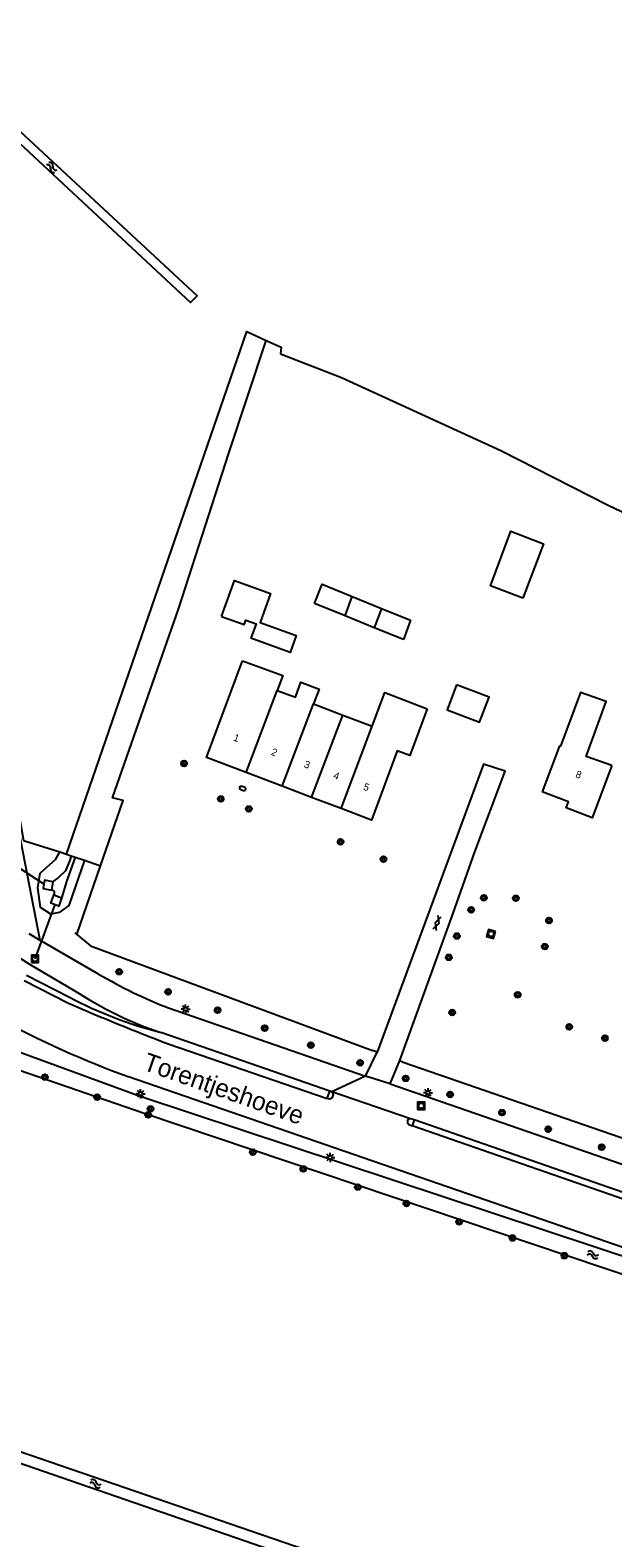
# Model space of a CAD drawing. Extents: x 135990 to 139000, y 393500 to 396000.
# Drawn here: x 136517.1 to 136597.2, y 395122 to 395329.5 of the extents above; entities that cross this region are included whole.
import ezdxf

# ---------------------------------------------------------------- set-up
doc = ezdxf.new("R2010")
doc.units = 0
for name, color, linetype in [('gg-afsc-draadraster', 7, 'Continuous'), ('gg-afsc-erfafscheiding', 7, 'Continuous'), ('gg-afsc-hekwerk', 7, 'Continuous'), ('gg-anno-huisnummerreeks BGT', 7, 'Continuous'), ('gg-anno-openbare ruimte label', 7, 'Continuous'), ('gg-bbg-bijgebouw', 7, 'Continuous'), ('gg-bbg-gedigitaliseerde bebouwing', 7, 'Continuous'), ('gg-bbg-gedigitaliseerde bijgebouw', 7, 'Continuous'), ('gg-bbg-hoofdgebouw', 7, 'Continuous'), ('gg-bbg-luifel en loopbrug', 7, 'Continuous'), ('gg-bbg-tussenscheiding', 7, 'Continuous'), ('gg-knt-bronhoudergrens', 7, 'Continuous'), ('gg-knt-verharding', 7, 'Continuous'), ('gg-knt-verharding nz', 7, 'Continuous'), ('gg-kntw-bovenkant insteek waterloop', 7, 'Continuous'), ('gg-kwrk-duiker nz buis', 7, 'Continuous'), ('gg-kwrk-faunavoorziening', 7, 'Continuous'), ('gt-grn-groengrens', 7, 'Continuous'), ('gt-grn-vlakafsluiter', 7, 'Continuous'), ('gt-grn-weggrens', 7, 'Continuous'), ('gt-symb-boom', 7, 'Continuous'), ('gt-symb-brandkraan', 7, 'Continuous'), ('gt-symb-gesloten verharding', 7, 'Continuous'), ('gt-symb-lichtmast', 7, 'Continuous'), ('gt-symb-rioolschacht', 7, 'Continuous'), ('gt-symb-watersymbool', 7, 'Continuous'), ('gx-grn-maaiveld', 7, 'Continuous')]:
    doc.layers.add(name, color=color, linetype=linetype)

# ---------------------------------------------------------------- blocks, each defined once
blk = doc.blocks.new('gt0-BOOM')
at = {"layer": 'gt-symb-boom'}
for radius in [0.4, 0.2]:
    blk.add_circle((0, 0), radius, dxfattribs=at)
blk = doc.blocks.new('gt0-BR')
at = {"layer": 'gt-symb-brandkraan'}
for centre, radius, start, end in [((-0.24, 0), 0.206, 107.5669, 252.4331), ((0.6, -2.66), 3, 106.892, 107.5669), ((0, -0.69), 0.938, 73.108, 106.892), ((-0.6, -2.66), 3, 72.4331, 73.108), ((0.24, 0), 0.206, 287.567, 72.4331), ((0.6, 2.66), 3, 252.4331, 253.108), ((0, 0.69), 0.938, 253.108, 286.8921), ((-0.6, 2.66), 3, 286.8921, 287.567)]:
    blk.add_arc(centre, radius, start, end, dxfattribs=at)
blk = doc.blocks.new('gt0-WA')
at = {"layer": 'gt-symb-watersymbool'}
for centre, start, end in [((-0.32, 0.02), 28.0725, 151.9275), ((0.43, 0.42), 208.0725, 331.9275), ((-0.32, -0.43), 28.0725, 151.9275), ((0.43, -0.03), 208.0725, 331.9275)]:
    blk.add_arc(centre, 0.425, start, end, dxfattribs=at)
blk = doc.blocks.new('gt0-RS')
at = {"layer": 'gt-symb-rioolschacht'}
blk.add_lwpolyline([(-0.5, -0.5), (0.5, -0.5), (0.5, 0.5), (-0.5, 0.5)], close=True, dxfattribs=at)
blk.add_circle((0, 0), 0.375, dxfattribs=at)
blk = doc.blocks.new('gt0-LMAST')
at = {"layer": 'gt-symb-lichtmast'}
for p, q in [((-0.18, 0.17), (-0.45, 0.44)), ((-0.01, 0.25), (-0.01, 0.62)), ((0.17, 0.17), (0.44, 0.44)), ((-0.26, 0), (-0.63, 0)), ((-0.18, -0.18), (-0.45, -0.45)), ((-0.01, -0.25), (-0.01, -0.63)), ((0.44, -0.45), (0.17, -0.18)), ((0.24, 0), (0.62, 0))]:
    blk.add_line(p, q, dxfattribs=at)
blk.add_circle((-0.01, 0), 0.25, dxfattribs=at)
blk = doc.blocks.new('gt0-GESVH1')
at = {"layer": 'gt-symb-gesloten verharding'}
for p, q in [((-0.99, -0.26), (0.01, 0.24)), ((0.01, -0.26), (-0.99, 0.24)), ((0.01, 0.24), (1.01, -0.26)), ((1.01, 0.24), (0.01, -0.26))]:
    blk.add_line(p, q, dxfattribs=at)

msp = doc.modelspace()

# ---------------------------------------------------------------- linework, layer by layer
at = {"layer": 'gg-afsc-draadraster'}
msp.add_lwpolyline([(136513.026, 395235.571), (136516.127, 395218.022), (136521.138, 395216.455)], dxfattribs=at)
at = {"layer": 'gg-afsc-erfafscheiding'}
msp.add_line((136523.466, 395205.085), (136526.733, 395214.516), dxfattribs=at)
for points in [[(136526.733, 395214.516), (136529.857, 395223.532), (136528.408, 395223.874), (136537.53, 395250), (136544.405, 395271.297), (136549.544, 395286.842)], [(136549.544, 395286.842), (136551.592, 395285.897), (136551.492, 395284.97), (136559.907, 395281.749)]]:
    msp.add_lwpolyline(points, dxfattribs=at)
at = {"layer": 'gg-afsc-hekwerk'}
for p, q in [((136523.195, 395205.314), (136523.466, 395205.085)), ((136568.379, 395187.481), (136612.594, 395172.192))]:
    msp.add_line(p, q, dxfattribs=at)
msp.add_lwpolyline([(136523.466, 395205.085), (136525.36, 395203.485), (136564.149, 395189.095)], dxfattribs=at)
msp.add_lwpolyline([(136523.466, 395205.085), (136525.36, 395203.485), (136564.149, 395189.095)], dxfattribs=at)
at = {"layer": 'gg-bbg-bijgebouw'}
msp.add_lwpolyline([(136543.406, 395248.86), (136546.527, 395247.753), (136546.734, 395248.337), (136548.161, 395247.837), (136547.443, 395245.845)], dxfattribs=at)
at = {"layer": 'gg-bbg-gedigitaliseerde bebouwing'}
for p, q in [((136556.03, 395236.797), (136560.08, 395235.264)), ((136560.08, 395235.264), (136564.129, 395233.731))]:
    msp.add_line(p, q, dxfattribs=at)
for points in [[(136546.283, 395242.74), (136551.852, 395240.731), (136551.073, 395238.673)], [(136551.073, 395238.673), (136553.551, 395237.735), (136554.33, 395239.793), (136556.809, 395238.854), (136556.03, 395236.797)], [(136564.129, 395233.731), (136565.88, 395238.356), (136571.714, 395236.147)], [(136597.125, 395228.316), (136593.591, 395229.589), (136596.305, 395237.12), (136592.813, 395238.379), (136590.028, 395230.973), (136589.916, 395231.015)]]:
    msp.add_lwpolyline(points, dxfattribs=at)
at = {"layer": 'gg-bbg-gedigitaliseerde bijgebouw'}
for p, q in [((136560.402, 395248.92), (136556.172, 395250.632)), ((136561.386, 395251.586), (136565.402, 395249.961)), ((136564.417, 395247.295), (136560.402, 395248.92)), ((136565.402, 395249.961), (136569.417, 395248.336)), ((136569.417, 395248.336), (136568.433, 395245.67)), ((136568.433, 395245.67), (136564.417, 395247.295))]:
    msp.add_line(p, q, dxfattribs=at)
for points in [[(136584.878, 395251.38), (136580.389, 395253.08), (136583.222, 395260.562), (136587.711, 395258.862), (136584.878, 395251.38)], [(136543.406, 395248.86), (136545.19, 395253.81), (136550.145, 395252.024), (136548.696, 395248.003), (136553.685, 395246.205), (136552.852, 395243.896), (136547.443, 395245.845)], [(136556.172, 395250.632), (136557.238, 395253.265), (136561.386, 395251.586)]]:
    msp.add_lwpolyline(points, dxfattribs=at)
at = {"layer": 'gg-bbg-hoofdgebouw'}
for p, q in [((136589.916, 395231.015), (136587.518, 395224.706)), ((136551.743, 395225.473), (136546.786, 395227.35)), ((136555.793, 395223.94), (136551.743, 395225.473)), ((136559.842, 395222.407), (136555.793, 395223.94))]:
    msp.add_line(p, q, dxfattribs=at)
for points in [[(136546.786, 395227.35), (136541.321, 395229.419), (136546.283, 395242.74)], [(136571.714, 395236.147), (136569.317, 395229.689), (136567.564, 395230.339), (136564.032, 395220.821), (136559.842, 395222.407)], [(136597.125, 395228.316), (136594.401, 395221.12), (136590.81, 395222.481), (136591.134, 395223.336), (136587.518, 395224.706)]]:
    msp.add_lwpolyline(points, dxfattribs=at)
at = {"layer": 'gg-bbg-luifel en loopbrug'}
msp.add_lwpolyline([(136575.737, 395239.448), (136574.427, 395235.988), (136578.916, 395234.288), (136580.226, 395237.749), (136575.737, 395239.448)], dxfattribs=at)
at = {"layer": 'gg-bbg-tussenscheiding'}
for p, q in [((136560.402, 395248.92), (136561.386, 395251.586)), ((136565.402, 395249.961), (136564.417, 395247.295)), ((136546.786, 395227.35), (136551.073, 395238.673)), ((136551.743, 395225.473), (136556.03, 395236.797)), ((136555.793, 395223.94), (136560.08, 395235.264)), ((136559.842, 395222.407), (136564.129, 395233.731))]:
    msp.add_line(p, q, dxfattribs=at)
at = {"layer": 'gg-knt-bronhoudergrens'}
for points in [[(136522.075, 395216.13), (136546.859, 395288.081), (136549.544, 395286.842)], [(136559.907, 395281.749), (136581.845, 395271.703), (136596.522, 395264.214), (136613.351, 395256.16), (136628.985, 395247.516), (136658.062, 395233.532), (136638.935, 395197.21), (136632.303, 395184.373)]]:
    msp.add_lwpolyline(points, dxfattribs=at)
at = {"layer": 'gg-knt-verharding'}
for p, q in [((136526.487, 395199.622), (136518.408, 395204.306)), ((136516.222, 395198.725), (136522.342, 395195.596)), ((136536.116, 395194.959), (136563.224, 395185.586)), ((136558.315, 395183.484), (136535.061, 395191.575)), ((136536.042, 395190.022), (136557.951, 395182.509)), ((136563.224, 395185.586), (136564.802, 395188.868)), ((136566.604, 395184.488), (136567.914, 395187.715)), ((136566.604, 395184.488), (136611.728, 395168.872)), ((136558.573, 395183.388), (136558.315, 395183.484)), ((136569.899, 395179.573), (136569.283, 395179.737)), ((136606.737, 395165.815), (136569.628, 395178.712)), ((136607.083, 395166.615), (136569.899, 395179.573))]:
    msp.add_line(p, q, dxfattribs=at)
for points in [[(136432.39, 395264.294), (136433.511, 395264.036), (136472.135, 395233.888), (136499.013, 395212.991), (136506.933, 395207.381), (136516.981, 395200.985), (136523.116, 395197.378)], [(136512.623, 395235.47), (136515.741, 395217.994), (136518.408, 395204.306)], [(136567.914, 395187.715), (136575.247, 395207.884), (136578.24, 395216.451), (136582.42, 395227.53), (136579.44, 395228.492), (136564.802, 395188.868)], [(136530.57, 395185.504), (136645.545, 395145.829), (136708.224, 395124.253)], [(136558.573, 395183.388), (136558.771, 395183.014), (136558.586, 395182.522), (136558.296, 395182.406), (136557.951, 395182.509)], [(136569.283, 395179.737), (136569.007, 395179.52), (136568.975, 395179.19), (136569.151, 395178.935), (136569.628, 395178.712)]]:
    msp.add_lwpolyline(points, dxfattribs=at)
for centre, radius, start, end in [((136558.725, 395253.92), 63.147, 239.30117, 249.02015), ((136551.211, 395240.013), 51.059, 236.61688, 251.56123), ((136664.516, 395525.414), 359.156, 246.68065, 249.04034), ((136577.879, 395314.973), 137.842, 241.75464, 249.92711)]:
    msp.add_arc(centre, radius, start, end, dxfattribs=at)
at = {"layer": 'gg-knt-verharding nz'}
for p, q in [((136516.896, 395205.183), (136518.408, 395204.306)), ((136566.604, 395184.488), (136563.224, 395185.586)), ((136569.283, 395179.737), (136558.573, 395183.388))]:
    msp.add_line(p, q, dxfattribs=at)
at = {"layer": 'gg-kntw-bovenkant insteek waterloop'}
for points in [[(136500.168, 395329.546), (136499.79, 395329.208), (136499.937, 395328.514), (136539.135, 395292.051), (136540.047, 395292.962), (136500.848, 395329.312), (136500.168, 395329.546)], [(136524.518, 395215.284), (136522.359, 395209.05), (136521.029, 395208.086), (136519.914, 395207.866), (136518.463, 395208.784), (136518.125, 395211.502), (136518.448, 395213.486), (136520.615, 395215.427), (136521.138, 395216.455)], [(136499.93, 395194.624), (136532.19, 395182.83), (136601.724, 395159.802)], [(136600.918, 395157.47), (136532.89, 395180.4), (136497.97, 395192.383)], [(136473.831, 395146.756), (136577.715, 395110.851), (136578.232, 395112.345), (136474.559, 395147.97), (136473.831, 395146.756)]]:
    msp.add_lwpolyline(points, dxfattribs=at)
at = {"layer": 'gg-kwrk-duiker nz buis'}
for p, q in [((136512.72, 395216.078), (136518.983, 395212.014)), ((136520.44, 395209.208), (136517.724, 395201.706))]:
    msp.add_line(p, q, dxfattribs=at)
at = {"layer": 'gg-kwrk-faunavoorziening'}
for p, q in [((136520.193, 395212.318), (136519.981, 395211.164)), ((136521.385, 395210.078), (136520.315, 395210.462))]:
    msp.add_line(p, q, dxfattribs=at)
for points in [[(136520.193, 395212.318), (136519.043, 395212.529), (136518.83, 395211.375), (136519.981, 395211.164)], [(136521.385, 395210.078), (136520.989, 395208.977), (136519.919, 395209.361), (136520.315, 395210.462)]]:
    msp.add_lwpolyline(points, dxfattribs=at)
at = {"layer": 'gt-grn-groengrens'}
for p, q in [((136516.535, 395199.461), (136522.487, 395196.419)), ((136557.951, 395182.509), (136558.315, 395183.484)), ((136569.899, 395179.573), (136569.628, 395178.712))]:
    msp.add_line(p, q, dxfattribs=at)
msp.add_arc((136549.656, 395248.201), 58.477, 242.31532, 255.54738, dxfattribs=at)
at = {"layer": 'gt-grn-vlakafsluiter'}
for p, q in [((136521.138, 395216.455), (136522.075, 395216.13)), ((136524.518, 395215.284), (136526.733, 395214.516)), ((136564.802, 395188.868), (136564.149, 395189.095)), ((136567.914, 395187.715), (136568.379, 395187.481))]:
    msp.add_line(p, q, dxfattribs=at)
at = {"layer": 'gt-grn-weggrens'}
msp.add_line((136563.224, 395185.586), (136558.573, 395183.388), dxfattribs=at)
at = {"layer": 'gx-grn-maaiveld'}
for p, q in [((136522.075, 395216.13), (136522.711, 395215.91)), ((136522.711, 395215.91), (136523.254, 395215.722)), ((136523.254, 395215.722), (136524.518, 395215.284))]:
    msp.add_line(p, q, dxfattribs=at)
for points in [[(136522.711, 395215.91), (136522.5, 395215.313), (136521.921, 395213.838), (136520.903, 395212.884), (136520.522, 395212.569), (136520.193, 395212.318)], [(136523.254, 395215.722), (136523.063, 395215.205), (136522.112, 395212.512), (136521.385, 395210.078)], [(136520.315, 395210.462), (136520.424, 395210.722), (136520.415, 395210.912), (136520.224, 395211.107), (136519.981, 395211.164)]]:
    msp.add_lwpolyline(points, dxfattribs=at)

# ---------------------------------------------------------------- block references
at = {"layer": 'gt-symb-boom'}
for p in [(136538.236, 395228.6), (136543.288, 395223.719), (136547.154, 395222.35), (136559.78, 395217.812), (136565.681, 395215.431), (136577.75, 395208.468), (136579.5, 395210.13), (136583.897, 395210.046), (136588.457, 395206.984), (136575.768, 395204.858), (136587.893, 395203.393), (136574.675, 395201.922), (136529.314, 395199.939), (136536.04, 395197.17), (136584.147, 395196.771), (136542.859, 395194.643), (136575.132, 395194.334), (136549.329, 395192.182), (136591.246, 395192.349), (136555.684, 395189.838), (136596.16, 395190.795), (136562.458, 395187.406), (136519.078, 395185.448), (136568.733, 395185.256), (136526.285, 395182.677), (136574.865, 395183.042), (136533.305, 395180.227), (136533.624, 395181.057), (136581.989, 395180.543), (136588.354, 395178.272), (136595.71, 395175.793), (136547.706, 395175.114), (136554.647, 395172.79), (136562.149, 395170.301), (136568.837, 395168.04), (136576.099, 395165.498), (136583.42, 395163.29), (136590.575, 395160.859)]:
    msp.add_blockref('gt0-BOOM', p, dxfattribs=at)
at = {"layer": 'gt-symb-brandkraan', "rotation": -18.779117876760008}
msp.add_blockref('gt0-BR', (136546.302, 395225.175), dxfattribs=at)
at = {"layer": 'gt-symb-gesloten verharding', "rotation": -109.9928939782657}
msp.add_blockref('gt0-GESVH1', (136573.077, 395206.65), dxfattribs=at)
at = {"layer": 'gt-symb-lichtmast'}
for p in [(136538.453, 395194.793), (136571.818, 395183.281), (136532.27, 395183.143), (136558.35, 395174.38)]:
    msp.add_blockref('gt0-LMAST', p, dxfattribs=at)
at = {"layer": 'gt-symb-rioolschacht', "rotation": 163.6136943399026}
msp.add_blockref('gt0-RS', (136580.494, 395205.143), dxfattribs=at)
at = {"layer": 'gt-symb-rioolschacht'}
for p in [(136517.724, 395201.706), (136570.87, 395181.489)]:
    msp.add_blockref('gt0-RS', p, dxfattribs=at)
at = {"layer": 'gt-symb-watersymbool'}
for p, rotation in [((136519.984, 395310.69), -42.93289678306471), ((136594.43, 395160.99), -12.006708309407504), ((136526.099, 395129.453), 160.91275549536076)]:
    msp.add_blockref('gt0-WA', p, dxfattribs=dict(at, rotation=rotation))

# ---------------------------------------------------------------- texts
at = {"layer": 'gg-anno-huisnummerreeks BGT'}
for s, p in [('1', (136544.93, 395231.794)), ('2', (136550.141, 395229.821)), ('3', (136554.644, 395228.116)), ('8', (136592.019, 395226.743)), ('4', (136558.694, 395226.583)), ('5', (136562.813, 395225.024))]:
    msp.add_text(s, height=1, rotation=339.3, dxfattribs=at).set_placement(p)
at = {"layer": 'gg-anno-openbare ruimte label'}
msp.add_text('Torentjeshoeve', height=2.5, rotation=340.6, dxfattribs=at).set_placement((136532.428, 395186.491))

doc.saveas('drawing.dxf')
